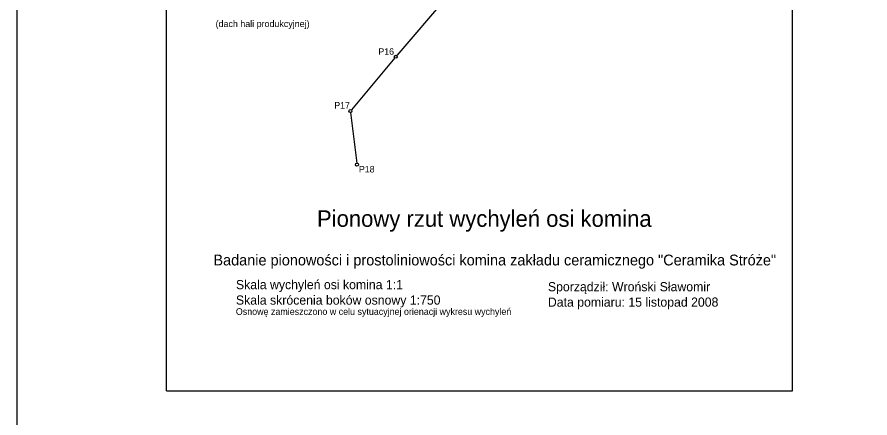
# Model space of a CAD drawing. Extents: x 138 to 6653, y -177 to 1520.
# Drawn here: x 137.94 to 166.54, y 1.58 to 15.03 of the extents above; entities that cross this region are included whole.
import ezdxf

# ---------------------------------------------------------------- set-up
doc = ezdxf.new("R2010")
doc.units = 0
for name, color, linetype in [('15 listopad 2008', 7, 'Continuous'), ('Opisy', 7, 'Continuous'), ('Ramka do drukowania', 7, 'Continuous'), ('Standart wykresów', 7, 'Continuous'), ('Wykresy 15 listopad 2008', 7, 'Continuous'), ('Wykresy 4 maj 2008', 7, 'Continuous')]:
    doc.layers.add(name, color=color, linetype=linetype)

msp = doc.modelspace()

# ---------------------------------------------------------------- linework, layer by layer
at = {"layer": '15 listopad 2008'}
msp.add_lwpolyline([(137.936, 38.661), (264.389, 38.661), (264.389, -75.347), (137.936, -75.347)], close=True, dxfattribs=at)
at = {"layer": 'Ramka do drukowania'}
for p, q in [((142.949, 2.492), (142.949, 32.192)), ((163.949, 2.492), (163.949, 32.192)), ((142.949, 2.492), (163.949, 2.492))]:
    msp.add_line(p, q, dxfattribs=at)
at = {"layer": 'Wykresy 15 listopad 2008'}
for p, q in [((153.283, 16.801), (150.668, 13.737)), ((150.604, 13.661), (149.148, 11.918)), ((149.122, 11.83), (149.33, 10.129))]:
    msp.add_line(p, q, dxfattribs=at)
for centre in [(150.636, 13.699), (149.116, 11.879), (149.336, 10.079)]:
    msp.add_circle(centre, 0.05, dxfattribs=at)

# ---------------------------------------------------------------- texts
at = {"layer": 'Opisy'}
for s, height, p in [('Pionowy rzut wychyleń osi komina', 0.55314, (147.995, 7.994)), ('Badanie pionowości i prostoliniowości komina zakładu ceramicznego "Ceramika Stróże"', 0.36281, (144.522, 6.699)), ('Skala wychyleń osi komina 1:1', 0.30766, (145.277, 5.902)), ('Sporządził: Wroński Sławomir', 0.30766, (155.74, 5.832)), ('Skala skrócenia boków osnowy 1:750', 0.30766, (145.277, 5.383)), ('Data pomiaru: 15 listopad 2008', 0.30766, (155.74, 5.315)), ('Osnowę zamieszczono w celu sytuacyjnej orienacji wykresu wychyleń', 0.22315, (145.274, 5.04))]:
    msp.add_text(s, height=height, dxfattribs=at).set_placement(p)
at = {"layer": 'Standart wykresów'}
msp.add_text('(dach hali produkcyjnej)', height=0.22315, dxfattribs=at).set_placement((144.595, 14.696))
at = {"layer": 'Wykresy 4 maj 2008'}
for s, p in [('P16', (150.055, 13.766)), ('P17', (148.576, 11.962)), ('P18', (149.402, 9.818))]:
    msp.add_text(s, height=0.22, dxfattribs=at).set_placement(p)

doc.saveas('drawing.dxf')
